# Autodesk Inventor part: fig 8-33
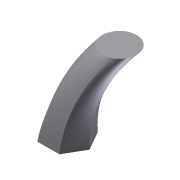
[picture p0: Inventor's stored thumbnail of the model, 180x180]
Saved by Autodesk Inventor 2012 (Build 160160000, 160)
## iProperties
Shininess: 77.0
Angle Display Precision: 2
Document Length Units: 11269
Document Angle Units: 11279
Document Time Units: 11290
Document Mass Units: 11283
Document Length Units Precision: 3
Document Angle Units Precision: 2
Created: 2001-12
Part Number: fig 8-33
Document SubType Name: Modeling
Designer: CADSoft
Density: 1 g/cm^3
Material: Default
Density: 0.0
Volumn: 0.0
Area: 0.0
PropertySet Name: Model Information
Control State: 0
Master: False
Checked Out: False
Author: CADSoft
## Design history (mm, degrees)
workplane "Work Plane3"
workplane "Work Plane4"
sketch "Sketch12"
  geometry: L1 (0, 10.598)-(9.178, -5.299); L2 (9.178, -5.299)-(-9.178, -5.299); L3 (-9.178, -5.299)-(0, 10.598); 1 further point
  constraints: 6 end point, 5 other
workplane "Work Plane5"
workplane "Work Plane6"
workplane "Work Plane7"
sketch "Sketch16"
  geometry: A1 r 72.799 centre (23.007, 110.594) between (0, 41.527) and (70, 54.995); 1 further point
  constraints: 2 point on circle, 1 centre point
loft "Loft5" sketch "Sketch16" dims "d57" = 0, "d58" = 90 deg, "d59" = 0, "d60" = 90 deg, "d61" = 0, "d62" = 90 deg
body "Solid2"
sketch "Sketch1"
  geometry: L1 (19.387, 0)-(9.693, -16.79); L2 (9.693, -16.79)-(-9.693, -16.79); L3 (-9.693, -16.79)-(-19.387, 0); L4 (-19.387, 0)-(-9.693, 16.79); L5 (-9.693, 16.79)-(9.693, 16.79); L6 (9.693, 16.79)-(19.387, 0); 1 further point
  constraints: 12 end point, 11 other
sketch "Sketch2"
  geometry: C1 r 15 at (23.06, 22.535)
  constraints: 1 centre point
